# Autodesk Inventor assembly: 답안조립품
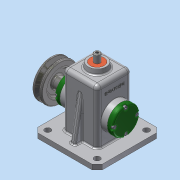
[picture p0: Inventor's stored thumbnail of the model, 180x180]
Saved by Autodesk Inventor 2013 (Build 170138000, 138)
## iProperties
Created: 2016-02
Part Number: 답안조립품
Document SubType Name: Assembly
Designer: ST1
Author: ST1
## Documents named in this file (15)
- C:\Users\ST1\Desktop\460211V1022\답안조립품.iam
- C:\Users\ST1\Desktop\460211V1022\1-본체.ipt
- C:\Users\ST1\Desktop\460211V1022\앞커버.ipt
- C:\Users\ST1\Desktop\460211V1022\뒤커버.ipt
- C:\Users\ST1\Desktop\460211V1022\베어링 12 x 32 x 10.ipt
- C:\Users\ST1\Desktop\460211V1022\편심축.ipt
- C:\Users\ST1\Desktop\460211V1022\링크.ipt
- C:\Users\ST1\Desktop\460211V1022\부시.ipt
- C:\Users\ST1\Desktop\460211V1022\슬라이드.ipt
- C:\Users\ST1\Desktop\460211V1022\핀 5 x 18.ipt
- C:\Users\ST1\Desktop\460211V1022\고정핀 1.2 x 10.ipt
- C:\Users\ST1\Desktop\460211V1022\키 4 x 4 x 10.ipt
- C:\Users\ST1\Desktop\460211V1022\V벨트풀리.ipt
- C:\Users\ST1\Desktop\460211V1022\멈춤나사 M3x8.ipt
- C:\Users\ST1\Desktop\460211V1022\볼트 M4 x 12.ipt
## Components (12 placed, 5 different names)
1. 1-본체:1
2. 핀 5 x 18:1
3. 고정핀 1.2 x 10:1
4. V벨트풀리:1
5. ISO 4762 M4 x 12:1
6. ISO 4762 M4 x 12:3
7. ISO 4762 M4 x 12:4
8. ISO 4762 M4 x 12:5
9. ISO 4762 M4 x 12:2
10. ISO 4762 M4 x 12:6
11. ISO 4762 M4 x 12:7
12. ISO 4762 M4 x 12:8
